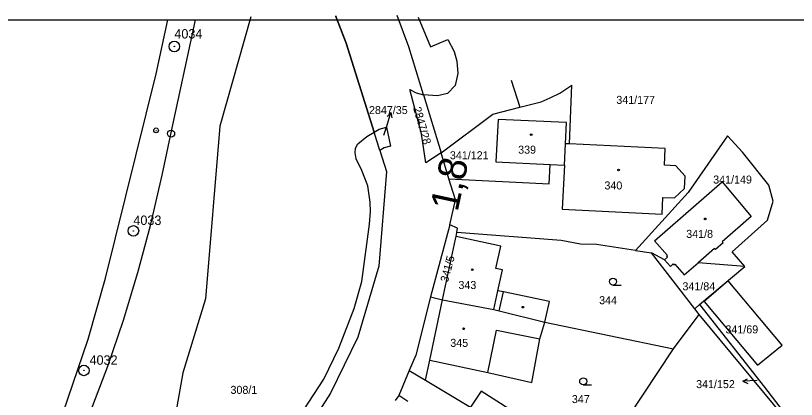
# Model space of a CAD drawing. Extents: x -558358 to -557517, y -1073785 to -1073189.
# Drawn here: x -558075.5 to -557909.7, y -1073270.7 to -1073189.2 of the extents above; entities that cross this region are included whole.
import ezdxf

# ---------------------------------------------------------------- set-up
doc = ezdxf.new("R2010")
doc.units = 0
for name, color, linetype in [('Hranice parcel', 7, 'Continuous'), ('Kolej', 7, 'Continuous'), ('Návěst místo trati', 7, 'Continuous'), ('Parcelní čísla', 7, 'Continuous'), ('Pop  PČ popisy', 7, 'Continuous'), ('Svazek obcí údolí Desné', 7, 'Continuous'), ('Vnitřní kresba', 7, 'Continuous'), ('Vrstva 1', 7, 'Continuous'), ('Vrstva 60', 7, 'Continuous'), ('Značky budov', 7, 'Continuous'), ('Značky kultur', 7, 'Continuous')]:
    doc.layers.add(name, color=color, linetype=linetype)

msp = doc.modelspace()

# ---------------------------------------------------------------- linework, layer by layer
at = {"layer": 'Hranice parcel'}
for p, q in [((-557970.23, -1073202.86), (-557968.43, -1073208.63)), ((-557957.84, -1073216.4), (-557957.38, -1073203.94)), ((-557990.44, -1073205.56), (-557988.88, -1073205.99)), ((-557988.88, -1073205.99), (-557985.13, -1073218.31)), ((-557985.87, -1073206.17), (-557988.88, -1073205.99)), ((-557974.16, -1073210.07), (-557968.43, -1073208.63)), ((-557985.13, -1073218.31), (-557974.16, -1073210.07)), ((-558000.9, -1073214.81), (-557999.34, -1073213.91)), ((-557999.34, -1073213.91), (-557998.27, -1073213.29)), ((-557998.11, -1073217.81), (-557999.34, -1073213.91)), ((-557924.3, -1073214.73), (-557932.67, -1073226.72)), ((-557958.95, -1073220.92), (-557958.74, -1073216.36)), ((-557957.84, -1073216.4), (-557958.74, -1073216.36)), ((-557997.23, -1073217.21), (-557998.11, -1073217.81)), ((-557985.13, -1073218.31), (-557988.34, -1073220.45)), ((-557983.46, -1073223.81), (-557985.13, -1073218.31)), ((-557961.95, -1073220.78), (-557958.95, -1073220.92)), ((-557932.67, -1073226.72), (-557943.85, -1073239.02)), ((-557983.29, -1073233.62), (-557987.36, -1073248.89)), ((-557981.96, -1073236.04), (-557981.79, -1073235.24)), ((-557943.85, -1073239.02), (-557940.47, -1073239.54)), ((-557931.28, -1073251.41), (-557940.47, -1073239.54)), ((-557937.69, -1073241), (-557940.47, -1073239.54)), ((-557920.64, -1073242.45), (-557930.56, -1073241.68)), ((-557930.24, -1073250.53), (-557920.64, -1073242.45)), ((-557987.36, -1073248.89), (-557984.8, -1073249.54)), ((-557931.28, -1073251.41), (-557930.24, -1073250.53)), ((-557935.78, -1073259.94), (-557930.32, -1073252.64)), ((-557930.32, -1073252.64), (-557931.28, -1073251.41)), ((-557909.08, -1073278.25), (-557930.32, -1073252.64)), ((-557963.13, -1073254.23), (-557935.78, -1073259.94)), ((-557954.2, -1073287.72), (-557935.78, -1073259.94)), ((-557991.89, -1073264.55), (-557994.13, -1073269.82)), ((-557991.89, -1073264.55), (-557988.45, -1073266.61)), ((-557988.45, -1073266.61), (-557978.88, -1073272.32)), ((-557994.13, -1073269.82), (-557994.86, -1073270.9)), ((-557992.18, -1073271.14), (-557994.13, -1073269.82))]:
    msp.add_line(p, q, dxfattribs=at)
for points in [[(-558007.54, -1073189.17), (-558005.3, -1073194.99), (-557999.34, -1073213.91)], [(-557988.88, -1073205.99), (-557991.98, -1073195.8), (-557994.44, -1073189.17)], [(-557990.03, -1073189.46), (-557987.35, -1073195.77), (-557983.68, -1073194.26), (-557982.33, -1073196.81), (-557981.76, -1073198.85), (-557981.57, -1073201.43), (-557982.14, -1073203.98), (-557983.75, -1073205.73), (-557985.87, -1073206.17)], [(-557988.34, -1073220.45), (-557989.32, -1073214.27), (-557991.8, -1073204.87), (-557990.44, -1073205.56)], [(-557968.43, -1073208.63), (-557963.9, -1073207.49), (-557961.96, -1073206.66), (-557959.95, -1073205.6), (-557957.38, -1073203.94)], [(-557958.74, -1073216.36), (-557958.53, -1073211.88), (-557973.01, -1073211.21), (-557973.48, -1073220.25), (-557961.95, -1073220.78)], [(-557998.27, -1073213.29), (-557996.72, -1073212.87), (-557995.91, -1073216.87), (-557997.23, -1073217.21)], [(-557920.64, -1073242.45), (-557923.35, -1073239.36), (-557915.81, -1073232.62), (-557914.61, -1073228.54), (-557915.51, -1073225.19), (-557921.13, -1073218.15), (-557924.3, -1073214.73)], [(-557958.95, -1073220.92), (-557959.44, -1073230.26), (-557938.22, -1073231.3), (-557938.05, -1073227.77), (-557935.56, -1073227.89), (-557933.42, -1073225.91), (-557933.29, -1073223.26), (-557935.3, -1073221.04), (-557937.72, -1073220.92), (-557937.55, -1073217.37), (-557957.84, -1073216.4)], [(-557998.11, -1073217.81), (-557996.7, -1073222.28), (-557998.38, -1073242.39), (-558002.78, -1073257.43), (-558008.62, -1073269.37), (-558024.06, -1073293.44), (-558032.02, -1073303.96), (-558033.31, -1073305.78)], [(-557983.46, -1073223.81), (-557962.16, -1073224.87), (-557961.95, -1073220.78)], [(-557983.29, -1073233.62), (-557982.1, -1073228.28), (-557983.46, -1073223.81)], [(-557937.69, -1073241), (-557937.08, -1073240.47), (-557937.28, -1073240.24), (-557937.09, -1073240.08), (-557939.85, -1073236.97), (-557925.45, -1073224.49), (-557919.26, -1073231.82), (-557925.44, -1073237.21), (-557925.27, -1073237.41), (-557926.88, -1073238.81), (-557927.05, -1073238.61), (-557930.56, -1073241.68)], [(-557981.79, -1073235.24), (-557981.67, -1073234.3), (-557983.29, -1073233.62)], [(-557984.8, -1073249.54), (-557982.04, -1073236.64), (-557981.96, -1073236.04)], [(-557963.13, -1073254.23), (-557962.1, -1073249.91), (-557971.91, -1073247.83), (-557973.07, -1073247.59), (-557972.12, -1073243.17), (-557973.48, -1073242.88), (-557972.48, -1073238.09), (-557981.96, -1073236.04)], [(-557943.85, -1073239.02), (-557952.12, -1073237.75), (-557955.56, -1073237.67), (-557959.65, -1073236.94), (-557981.79, -1073235.24)], [(-557937.69, -1073241), (-557936.45, -1073242.42), (-557935.84, -1073241.9), (-557935.68, -1073242.09), (-557935.49, -1073241.92), (-557933.49, -1073244.23), (-557930.56, -1073241.68)], [(-557912.73, -1073259.16), (-557924.17, -1073245.52), (-557929.3, -1073249.85), (-557917.91, -1073263.41), (-557912.73, -1073259.16)], [(-557987.36, -1073248.89), (-557990.48, -1073261.24), (-557991.89, -1073264.55)], [(-557984.8, -1073249.54), (-557973.92, -1073251.6), (-557972.79, -1073251.88), (-557963.13, -1073254.23)], [(-557930.24, -1073250.53), (-557916.49, -1073268.06), (-557909.46, -1073277.19)], [(-557988.45, -1073266.61), (-557987.54, -1073262.34), (-557975.19, -1073264.98), (-557965.84, -1073267.06), (-557964.16, -1073257.82), (-557963.13, -1073254.23)], [(-557973.02, -1073276.12), (-557970.72, -1073272.68), (-557976.62, -1073268.9), (-557978.88, -1073272.32)]]:
    msp.add_lwpolyline(points, dxfattribs=at)
at = {"layer": 'Kolej'}
msp.add_lwpolyline([(-558079.04, -1073313.09), (-558073.77, -1073303.7), (-558068.68, -1073293.77), (-558063.96, -1073283.66), (-558059.66, -1073273.45), (-558055.92, -1073263.64), (-558052.59, -1073253.84), (-558049.52, -1073243.71), (-558046.86, -1073233.73), (-558044.36, -1073223.02), (-558042.07, -1073212.37), (-558037.79, -1073192.43), (-558037.29, -1073190.09)], dxfattribs=at)
at = {"layer": 'Návěst místo trati'}
msp.add_line((-558045.69, -1073213.53), (-558045.59, -1073213.53), dxfattribs=at)
for centre, radius in [((-558045.64, -1073213.53), 0.5), ((-558042.46, -1073214.22), 0.75)]:
    msp.add_circle(centre, radius, dxfattribs=at)
at = {"layer": 'Pop  PČ popisy'}
for p, q in [((-557996.68, -1073212.64), (-557995.8, -1073209.77)), ((-557995.8, -1073209.77), (-557996.57, -1073210.58)), ((-557995.8, -1073209.77), (-557995.62, -1073210.87)), ((-557997.26, -1073214.56), (-557996.68, -1073212.64)), ((-557921.05, -1073266.82), (-557920.07, -1073266.27)), ((-557918.05, -1073266.66), (-557921.05, -1073266.82)), ((-557921.05, -1073266.82), (-557920.02, -1073267.27))]:
    msp.add_line(p, q, dxfattribs=at)
at = {"layer": 'Svazek obcí údolí Desné'}
for points in [[(-558025.53, -1073189.39), (-558032.09, -1073212.63), (-558035.15, -1073249.33), (-558039.97, -1073265.01), (-558041.24, -1073272.26), (-558045.55, -1073290.79), (-558055.77, -1073312.33), (-558066.64, -1073329.29), (-558067.37, -1073328.67), (-558071.91, -1073335.47), (-558071.45, -1073339.78), (-558072.38, -1073341.74), (-558078.52, -1073350.81)], [(-558066.74, -1073350.64), (-558065.9, -1073348.86), (-558061.08, -1073328.44), (-558060.65, -1073327.54), (-558046.7, -1073313.29), (-558030.4, -1073296.27), (-558015.33, -1073274.48), (-558010.02, -1073266.4), (-558006.82, -1073259.79), (-558003.58, -1073251.39), (-558001.93, -1073245.63), (-558000.3, -1073233.47), (-558000.14, -1073230.76), (-558000.21, -1073228.76), (-558000.67, -1073225.31), (-558001.93, -1073222.03), (-558003.18, -1073219.55), (-558003.41, -1073218.32), (-558003.28, -1073217.31), (-558002.8, -1073216.38), (-558000.9, -1073214.81), (-557999.34, -1073213.91), (-558005.3, -1073194.99), (-558007.47, -1073189.35)], [(-558082.18, -1073306.93), (-558073.77, -1073292.96), (-558066.53, -1073276.76), (-558060.05, -1073257.85), (-558056.4, -1073244.89), (-558045.6, -1073201.5), (-558043.17, -1073190.09)]]:
    msp.add_lwpolyline(points, dxfattribs=at)
at = {"layer": 'Vnitřní kresba'}
for p, q in [((-557973.92, -1073251.6), (-557973.07, -1073247.59)), ((-557972.79, -1073251.88), (-557971.91, -1073247.83)), ((-557987.54, -1073262.34), (-557984.8, -1073249.54)), ((-557975.19, -1073264.98), (-557973.4, -1073255.98)), ((-557973.4, -1073255.98), (-557964.16, -1073257.82))]:
    msp.add_line(p, q, dxfattribs=at)
at = {"layer": 'Vrstva 1'}
msp.add_line((-558357.53, -1073190.09), (-557516.53, -1073190.09), dxfattribs=at)
at = {"layer": 'Vrstva 60'}
for p, q in [((-558041.77, -1073195.72), (-558041.77, -1073195.72)), ((-558041.77, -1073195.72), (-558041.77, -1073195.72)), ((-558050.47, -1073234.88), (-558050.47, -1073234.88)), ((-558050.47, -1073234.88), (-558050.47, -1073234.88)), ((-558060.98, -1073264.51), (-558060.98, -1073264.51)), ((-558060.98, -1073264.51), (-558060.98, -1073264.51))]:
    msp.add_line(p, q, dxfattribs=at)
for centre, radius in [((-558041.77, -1073195.72), 1.12), ((-558041.77, -1073195.72), 0.045), ((-558050.47, -1073234.88), 1.12), ((-558050.47, -1073234.88), 0.045), ((-558060.98, -1073264.51), 1.12), ((-558060.98, -1073264.51), 0.045)]:
    msp.add_circle(centre, radius, dxfattribs=at)
at = {"layer": 'Značky budov'}
for centre in [(-557965.99, -1073214.44), (-557947.45, -1073221.95), (-557929.04, -1073232.33), (-557978.51, -1073243.13), (-557967.78, -1073251.08), (-557980.34, -1073255.67)]:
    msp.add_circle(centre, 0.175, dxfattribs=at)
at = {"layer": 'Značky kultur'}
for p, q in [((-557948.63, -1073246.4), (-557946.88, -1073246.4)), ((-557954.95, -1073267.58), (-557953.2, -1073267.58))]:
    msp.add_line(p, q, dxfattribs=at)
for centre in [(-557948.63, -1073245.65), (-557954.95, -1073266.83)]:
    msp.add_circle(centre, 0.75, dxfattribs=at)

# ---------------------------------------------------------------- texts
at = {"layer": 'Návěst místo trati'}
msp.add_text('1,8', height=6, rotation=77.8693, dxfattribs=at).set_placement((-557981.63, -1073230.98))
at = {"layer": 'Parcelní čísla'}
for s, p in [('341/177', (-557947.92, -1073207.91)), ('2847/35', (-558000.44, -1073210.07)), ('341/121', (-557983.26, -1073219.67)), ('339', (-557968.77, -1073218.49)), ('341/149', (-557927.35, -1073224.83)), ('340', (-557950.45, -1073226.08)), ('341/8', (-557933.08, -1073236.37)), ('343', (-557981.45, -1073247.22)), ('341/84', (-557933.88, -1073247.5)), ('344', (-557951.57, -1073250.45)), ('341/69', (-557924.75, -1073256.65)), ('345', (-557983.18, -1073259.51)), ('308/1', (-558029.85, -1073269.49)), ('341/152', (-557930.98, -1073268.27)), ('347', (-557957.36, -1073271.45))]:
    msp.add_text(s, height=1.7, dxfattribs=at).set_placement(p)
for s, rotation, p in [('2847/28', 286, (-557991.1, -1073208.79)), ('341/5', 75, (-557983.69, -1073245.9))]:
    msp.add_text(s, height=1.7, rotation=rotation, dxfattribs=at).set_placement(p)
at = {"layer": 'Vrstva 60'}
for s, p in [('4034', (-558041.77, -1073194.03)), ('4033', (-558050.47, -1073233.62)), ('4032', (-558059.78, -1073263.31))]:
    msp.add_text(s, height=2, dxfattribs=at).set_placement(p)

doc.saveas('drawing.dxf')
